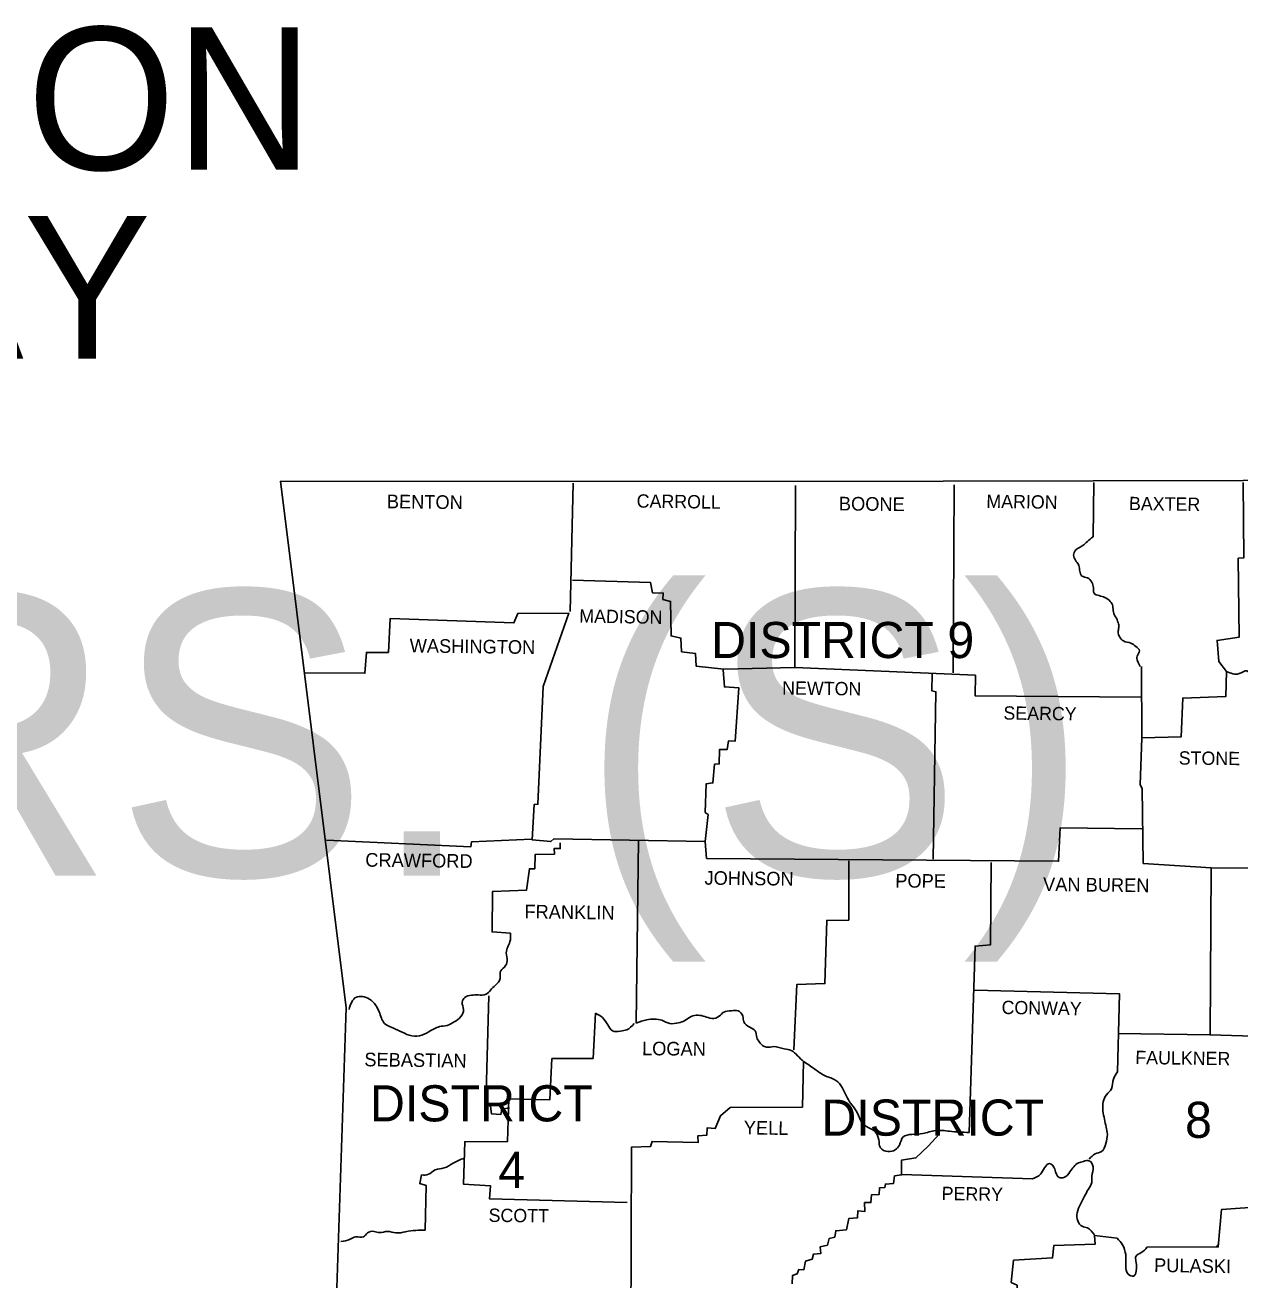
# Model space of a CAD drawing. Extents: x 1373884 to 1376992, y 1168426 to 1170473.
# Drawn here: x 1376215 to 1376598.2, y 1170029.4 to 1170425.3 of the extents above; entities that cross this region are included whole.
import ezdxf

# ---------------------------------------------------------------- set-up
doc = ezdxf.new("R2010")
doc.units = 0
doc.layers.add('R_Draft', color=7, linetype='Continuous')

msp = doc.modelspace()

# ---------------------------------------------------------------- linework, layer by layer
at = {"layer": 'R_Draft'}
for points in [[(1376295.59, 1170281.4), (1376457.29, 1170281.3), (1376599.19, 1170281.6), (1376766.59, 1170284.2), (1376844.19, 1170286)], [(1376307.29, 1169843.9), (1376316.29, 1170115.2), (1376295.59, 1170281.4)], [(1376387.89, 1170280.8), (1376386.99, 1170240.3)], [(1376387.69, 1170250.2), (1376412.29, 1170249.4), (1376412.89, 1170246.2), (1376416.29, 1170246.1), (1376416.19, 1170244.1), (1376418.59, 1170243.5), (1376418.79, 1170232.6), (1376421.89, 1170231.9), (1376422.09, 1170227.6), (1376426.49, 1170227), (1376426.69, 1170223), (1376435.39, 1170222.1), (1376457.79, 1170222.6), (1376457.99, 1170280.1)], [(1376508.09, 1170280.3), (1376507.79, 1170220.9)], [(1376552.09, 1170281), (1376551.89, 1170263.9)], [(1376568.89, 1170039.7), (1376591.39, 1170039.8), (1376592.39, 1170051.6), (1376605.79, 1170052.6), (1376605.79, 1170106.2), (1376588.79, 1170106.7), (1376589.09, 1170159.4), (1376567.69, 1170160.8), (1376567.39, 1170184.4), (1376566.69, 1170185.6), (1376567.29, 1170200.4), (1376579.69, 1170200.8), (1376580.19, 1170213), (1376593.79, 1170213.5), (1376593.99, 1170221.4), (1376591.59, 1170224.5), (1376590.99, 1170231.2), (1376597.99, 1170232.2), (1376597.69, 1170257.1), (1376599.39, 1170257.2), (1376599.19, 1170281)], [(1376429.99, 1170162.4), (1376429.49, 1170167.7), (1376381.79, 1170168.6), (1376380.89, 1170167.7), (1376374.99, 1170168.2), (1376375.59, 1170179.4), (1376376.79, 1170179.5), (1376378.39, 1170216.6), (1376386.49, 1170239.8), (1376370.39, 1170239.7), (1376369.19, 1170236.7), (1376330.19, 1170238.1), (1376329.59, 1170227.4), (1376322.69, 1170227.4), (1376322.19, 1170220.8), (1376303.49, 1170220.9)], [(1376457.79, 1170222.6), (1376514.79, 1170220.2), (1376514.69, 1170213.7), (1376566.99, 1170213.3)], [(1376567.29, 1170200.4), (1376567.19, 1170222.9)], [(1376435.19, 1170221.9), (1376435.59, 1170216.5), (1376440.19, 1170216.2), (1376438.99, 1170199.4), (1376436.89, 1170199.5), (1376436.49, 1170196.8), (1376434.09, 1170196.8), (1376433.99, 1170192.2), (1376432.49, 1170192.1), (1376431.99, 1170186.2), (1376429.79, 1170185.9), (1376429.49, 1170176.9), (1376430.49, 1170176.2), (1376429.49, 1170167.7)], [(1376501.09, 1170220.5), (1376500.99, 1170215.3), (1376502.29, 1170215), (1376501.49, 1170162.2)], [(1376567.29, 1170171.7), (1376541.49, 1170172), (1376540.99, 1170161.5), (1376429.99, 1170162.4)], [(1376310.09, 1170168.1), (1376355.59, 1170166), (1376355.79, 1170167.6), (1376374.79, 1170168.5)], [(1376383.79, 1170167.3), (1376383.79, 1170165.5), (1376381.89, 1170165.5), (1376381.99, 1170163.7), (1376375.89, 1170163.6), (1376375.79, 1170159.1), (1376374.09, 1170159.1), (1376373.19, 1170152.4), (1376362.39, 1170151.9), (1376362.29, 1170139.2), (1376368.09, 1170138.8)], [(1376407.79, 1170110.4), (1376408.49, 1170168.1)], [(1376474.89, 1170161.6), (1376474.79, 1170142.9), (1376467.89, 1170142.8), (1376467.29, 1170122.9), (1376458.49, 1170122.6), (1376457.49, 1170102)], [(1376519.69, 1170161.1), (1376519.49, 1170135.1), (1376514.69, 1170134.7), (1376512.79, 1170075.9)], [(1376589.09, 1170159.4), (1376640.49, 1170159.1), (1376644.89, 1170161.2), (1376644.59, 1170122.1), (1376641.59, 1170120.8), (1376638.89, 1170118.5), (1376637.99, 1170117.6), (1376637.89, 1170106.4), (1376605.19, 1170106.4)], [(1376514.49, 1170120.8), (1376560.19, 1170119.7), (1376559.59, 1170095)], [(1376361.29, 1170119), (1376360.29, 1170084.6), (1376361.79, 1170084.2), (1376362.09, 1170081.8), (1376365.09, 1170081.6), (1376365.39, 1170083.3), (1376367.79, 1170083.7)], [(1376394.89, 1170113.6), (1376394.19, 1170099.3), (1376381.19, 1170099.2), (1376380.49, 1170086.2), (1376367.59, 1170086.5), (1376367.19, 1170073.1), (1376353.69, 1170073), (1376353.29, 1170059.6), (1376361.79, 1170059.1), (1376361.49, 1170055), (1376404.89, 1170053.8)], [(1376559.69, 1170107.1), (1376588.79, 1170106.7)], [(1376406.09, 1170012.8), (1376406.29, 1170071.3), (1376412.29, 1170071.5), (1376412.79, 1170073.1), (1376427.29, 1170072.7), (1376427.19, 1170074.8), (1376430.09, 1170075.1), (1376430.19, 1170077.4), (1376432.69, 1170077.2), (1376434.39, 1170081.2), (1376437.39, 1170083.8), (1376460.19, 1170083.9), (1376460.59, 1170098.3)], [(1376503.49, 1170075.5), (1376499.89, 1170071.6), (1376495.99, 1170067.9), (1376491.49, 1170067.2), (1376491.49, 1170062.5), (1376489.29, 1170062.2), (1376488.89, 1170059.8), (1376486.39, 1170059.6), (1376486.19, 1170058.5), (1376484.49, 1170058.4), (1376484.39, 1170056.3), (1376481.99, 1170056.2), (1376481.79, 1170053.8), (1376479.79, 1170053.8), (1376479.89, 1170051), (1376477.69, 1170051.2), (1376477.59, 1170049), (1376474.89, 1170048.8), (1376474.09, 1170045.2), (1376470.69, 1170044.9), (1376470.39, 1170042.9), (1376468.59, 1170042.4), (1376468.09, 1170040.3), (1376465.79, 1170039.8), (1376465.99, 1170037.7), (1376463.69, 1170037.5), (1376463.29, 1170035.9), (1376461.19, 1170035.3), (1376460.69, 1170032.6), (1376459.09, 1170032.7), (1376458.59, 1170031.3), (1376457.09, 1170030.8), (1376456.99, 1170028.1)], [(1376341.19, 1170045.1), (1376341.49, 1170059.2), (1376339.49, 1170059.8), (1376340.09, 1170062.5)], [(1376532.79, 1170061.3), (1376491.59, 1170062.6)], [(1376527.89, 1170023.1), (1376527.89, 1170027.7), (1376526.09, 1170028.6), (1376526.79, 1170035.6), (1376539.09, 1170036.3), (1376539.49, 1170040.2), (1376552.59, 1170040.7), (1376552.29, 1170043.4), (1376559.49, 1170042.6)], [(1376590.89, 1170039.9), (1376591.39, 1170040.4)]]:
    msp.add_lwpolyline(points, dxfattribs=at)
for points in [[(1376551.89, 1170263.9), (1376550.09, 1170262.4), (1376548.49, 1170261), (1376546.09, 1170259.3), (1376545.79, 1170257.7), (1376546.59, 1170256.1), (1376547.39, 1170254.8), (1376547.69, 1170253), (1376548.39, 1170251.5), (1376550.09, 1170250.9), (1376551.49, 1170249.6), (1376551.99, 1170247.8), (1376552.19, 1170246.1), (1376553.79, 1170245.3), (1376555.59, 1170244.7), (1376557.29, 1170243.5), (1376558.09, 1170242), (1376558.29, 1170240.1), (1376558.99, 1170238.6), (1376559.79, 1170236.8), (1376559.99, 1170235.3), (1376559.79, 1170233.8), (1376560.19, 1170232.4), (1376561.49, 1170231), (1376563.79, 1170230.3), (1376565.39, 1170229.3), (1376566.49, 1170227.9), (1376565.79, 1170226.2), (1376565.89, 1170224.7), (1376566.79, 1170222.9)], [(1376593.99, 1170221.4), (1376597.99, 1170220.7), (1376600.39, 1170221.6), (1376602.09, 1170219), (1376602.99, 1170217), (1376604.49, 1170214.1), (1376606.89, 1170213.2), (1376608.69, 1170211.6), (1376608.69, 1170209.9), (1376607.09, 1170208.3), (1376605.89, 1170206.7), (1376606.29, 1170204.8), (1376606.69, 1170202.2), (1376606.69, 1170199.7), (1376606.09, 1170197.4), (1376605.59, 1170195.3), (1376606.09, 1170193.5), (1376607.99, 1170193.8), (1376609.99, 1170195.3), (1376612.09, 1170195.3), (1376614.09, 1170194.2), (1376616.19, 1170192.3), (1376618.29, 1170192.7), (1376619.99, 1170193.2), (1376622.39, 1170193.9), (1376624.09, 1170193), (1376625.59, 1170191.8), (1376627.39, 1170189.9), (1376629.09, 1170188.7), (1376631.29, 1170187.6), (1376633.99, 1170186.9), (1376636.49, 1170185.2), (1376636.89, 1170182.3), (1376636.79, 1170179.8), (1376636.59, 1170176.7), (1376636.39, 1170173.3), (1376636.69, 1170170), (1376637.79, 1170167.8), (1376639.19, 1170165.2), (1376639.59, 1170162.8), (1376639.49, 1170159)], [(1376368.09, 1170138.8), (1376368.09, 1170136.7), (1376367.29, 1170134.5), (1376366.79, 1170132.6), (1376367.09, 1170130.1), (1376366.19, 1170128.1), (1376364.89, 1170126.5), (1376364.89, 1170124.5), (1376363.39, 1170122.4), (1376361.79, 1170120.8), (1376360.39, 1170119.5), (1376357.89, 1170119.3), (1376355.79, 1170119.2), (1376353.69, 1170118.5), (1376352.89, 1170117), (1376353.29, 1170114.7), (1376352.49, 1170112.5), (1376350.39, 1170110.8), (1376348.09, 1170109.7), (1376345.69, 1170109.3), (1376342.39, 1170107.7), (1376339.39, 1170106.4), (1376336.19, 1170106.6), (1376333.19, 1170107.9), (1376330.49, 1170109.1), (1376328.39, 1170110.3), (1376326.69, 1170114), (1376325.59, 1170116), (1376323.69, 1170118), (1376321.39, 1170118.8), (1376319.49, 1170118.6), (1376317.19, 1170114.7)], [(1376394.89, 1170113.6), (1376397.09, 1170112.2), (1376398.79, 1170109.9), (1376400.29, 1170108), (1376402.79, 1170107.9), (1376404.79, 1170108.3), (1376407.09, 1170110.3)], [(1376460.59, 1170098.3), (1376458.69, 1170100.1), (1376456.69, 1170101.8), (1376454.49, 1170102.3), (1376451.09, 1170103), (1376448.89, 1170102.8), (1376447.59, 1170103.4), (1376446.69, 1170104.4), (1376445.79, 1170105.9), (1376445.29, 1170108), (1376443.59, 1170109.1), (1376441.69, 1170110.8), (1376441.39, 1170112.6), (1376439.89, 1170114.3), (1376437.79, 1170114.3), (1376435.39, 1170113.9), (1376433.99, 1170112.6), (1376431.59, 1170111.9), (1376429.39, 1170112.5), (1376427.29, 1170112.9), (1376425.09, 1170112.5), (1376423.09, 1170111.2), (1376421.09, 1170110.5), (1376418.39, 1170110.3), (1376415.89, 1170111.3), (1376413.49, 1170111.7), (1376411.09, 1170111.5), (1376407.79, 1170110.4)], [(1376460.59, 1170098.3), (1376464.09, 1170095.9), (1376467.39, 1170093.8), (1376470.79, 1170092.3), (1376472.69, 1170090.1), (1376474.39, 1170086.7), (1376475.79, 1170084.6), (1376477.59, 1170082), (1376478.89, 1170079.1), (1376480.99, 1170077.5), (1376483.19, 1170076.1), (1376484.29, 1170073.6), (1376484.79, 1170071.1), (1376487.19, 1170069.9), (1376489.49, 1170070.4), (1376490.79, 1170071.9), (1376491.99, 1170074.5), (1376494.69, 1170075.3), (1376498.19, 1170075.6), (1376502.19, 1170076.5), (1376506.59, 1170076.3), (1376512.79, 1170075.9)], [(1376559.59, 1170095), (1376558.29, 1170092.7), (1376557.69, 1170089.7), (1376556.09, 1170087.8), (1376555.09, 1170085.6), (1376554.99, 1170082.7), (1376555.49, 1170080.1), (1376555.99, 1170077.6), (1376556.39, 1170075.3), (1376555.89, 1170072.4), (1376554.59, 1170069.9), (1376552.59, 1170069.2), (1376550.69, 1170067.5)], [(1376340.09, 1170062.5), (1376342.29, 1170062.7), (1376344.39, 1170064.1), (1376347.19, 1170064.7), (1376349.99, 1170066.2), (1376353.49, 1170067.8)], [(1376532.79, 1170061.3), (1376535.29, 1170062.7), (1376536.59, 1170064.8), (1376538.19, 1170066.1), (1376539.79, 1170064.3), (1376541.19, 1170061.7), (1376542.69, 1170061.7), (1376544.59, 1170063.5), (1376545.79, 1170065.1), (1376547.29, 1170066.3), (1376548.89, 1170066.8), (1376550.59, 1170067), (1376551.89, 1170065.1), (1376551.49, 1170062.1), (1376551.49, 1170060.1), (1376550.39, 1170058), (1376549.19, 1170055.8), (1376547.89, 1170053.3), (1376546.89, 1170050.6), (1376547.09, 1170048), (1376548.49, 1170046.3), (1376550.09, 1170045.8), (1376552.29, 1170043.6)], [(1376341.19, 1170045.1), (1376338.29, 1170045), (1376334.99, 1170044.6), (1376331.99, 1170044.2), (1376329.29, 1170044.7), (1376326.79, 1170044.3), (1376325.09, 1170044.7), (1376322.99, 1170044.2), (1376321.79, 1170043), (1376319.29, 1170043), (1376317.49, 1170042.2), (1376314.59, 1170041.5)], [(1376559.49, 1170042.6), (1376561.19, 1170040.4), (1376562.19, 1170037.4), (1376562.19, 1170034), (1376562.99, 1170031.2), (1376564.59, 1170030.6), (1376565.59, 1170033), (1376565.39, 1170035.4), (1376565.39, 1170036.8), (1376567.09, 1170038), (1376568.89, 1170039.7)]]:
    msp.add_spline(points, degree=3, dxfattribs=at)

# ---------------------------------------------------------------- texts
for s, height, p in [('ARKANSAS DEPARTMENT OF TRANSPORTATION ', 45, (1374874.9, 1170379.67)), ('CONSTRUCTION PLANS FOR STATE HIGHWAY', 45, (1374897.32, 1170320.07)), ('LONG LAKE STR. & APPRS. (S)', 90, (1374778.41, 1170156.89)), ('DISTRICT 9', 11.4, (1376431.39, 1170225.6)), ('DISTRICT', 11.4, (1376323.79, 1170079.4)), ('DISTRICT', 11.4, (1376466.19, 1170074.9)), ('8', 11.4, (1376580.89, 1170074.2)), ('4', 11.4, (1376364.29, 1170058.4))]:
    msp.add_text(s, height=height, dxfattribs=at).set_placement(p)
for s, height, rotation, p in [('BENTON', 4.301, 359.2527, (1376329.09, 1170272.9)), ('CARROLL', 4.201, 359.1481, (1376407.89, 1170273.1)), ('BOONE', 4.301, 359.4001, (1376471.69, 1170272.2)), ('MARION', 4.201, 359.1854, (1376518.19, 1170273)), ('BAXTER', 4.201, 359.2559, (1376563.19, 1170272.3)), ('MADISON', 4.201, 359.0906, (1376389.79, 1170236.8)), ('WASHINGTON', 4.3, 359.232, (1376336.29, 1170227.4)), ('NEWTON', 4.201, 359.2717, (1376453.79, 1170214.1)), ('SEARCY', 4.199, 359.2527, (1376523.59, 1170206.2)), ('STONE', 4.199, 359.4001, (1376578.89, 1170192)), ('CRAWFORD', 4.3, 359.2771, (1376322.29, 1170159.8)), ('JOHNSON', 4.301, 359.3514, (1376429.29, 1170154.1)), ('POPE', 4.301, 359.6155, (1376489.49, 1170153.2)), ('VAN BUREN', 4.301, 359.3508, (1376536.09, 1170152.1)), ('FRANKLIN', 4.301, 359.1815, (1376372.49, 1170143.5)), ('CONWAY', 4.199, 359.0371, (1376522.99, 1170113.3)), ('LOGAN', 4.301, 359.3969, (1376409.59, 1170100.3)), ('SEBASTIAN', 4.3, 359.2816, (1376321.99, 1170096.8)), ('FAULKNER', 4.201, 359.2486, (1376565.19, 1170097.5)), ('YELL', 4.301, 359.1987, (1376441.69, 1170075.3)), ('PERRY', 4.201, 359.0858, (1376504.09, 1170054.6)), ('SCOTT', 4.201, 359.4063, (1376361.19, 1170047.7)), ('PULASKI', 4.301, 359.053, (1376571.09, 1170031.9))]:
    msp.add_text(s, height=height, rotation=rotation, dxfattribs=at).set_placement(p)

doc.saveas('drawing.dxf')
